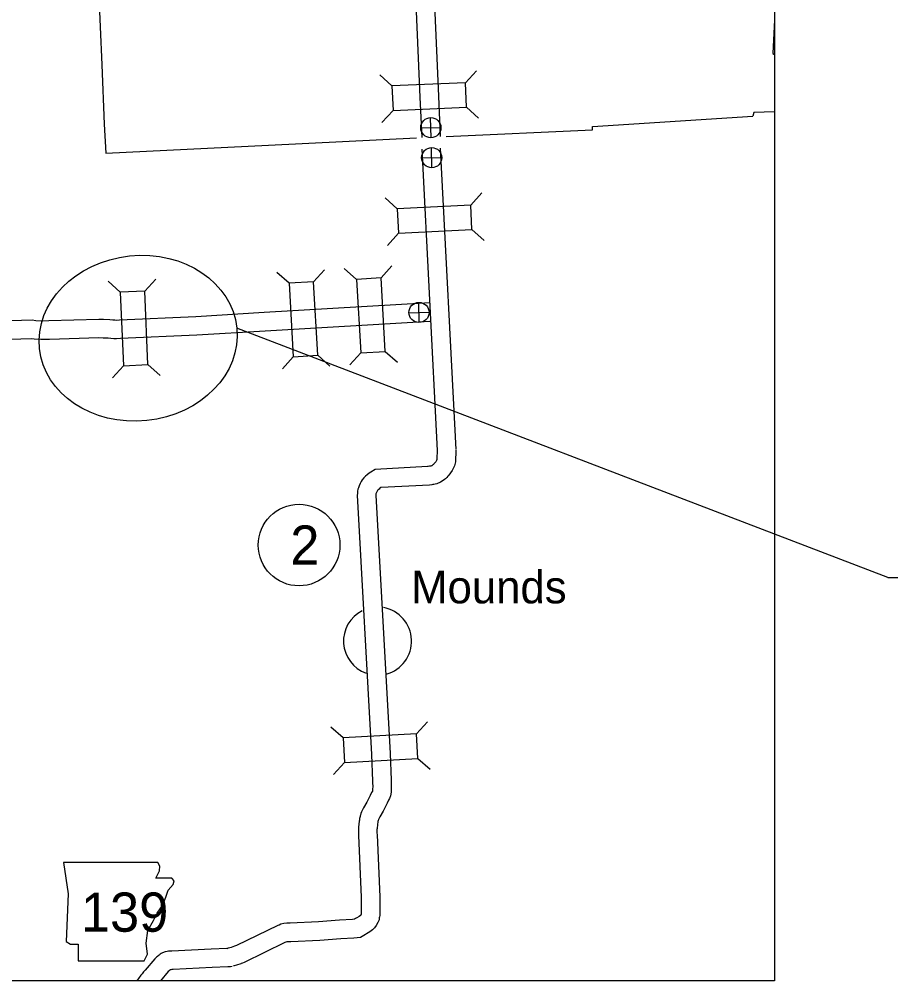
# Model space of a CAD drawing. Extents: x -0.3 to 2.65, y 0 to 1.9.
# Drawn here: x 0.2273 to 0.3593, y 0.5417 to 0.6874 of the extents above; entities that cross this region are included whole.
import ezdxf

# ---------------------------------------------------------------- set-up
doc = ezdxf.new("R2010")
doc.units = 0
for name, color, linetype in [('Default', 7, 'Continuous'), ('DSN_DRFT_DNC', 7, 'Continuous'), ('Level 21', 7, 'Continuous'), ('Level 22', 7, 'Continuous'), ('Level 23', 7, 'Continuous'), ('Level 24', 7, 'Continuous'), ('Level 38', 7, 'Continuous'), ('Level 39', 7, 'Continuous'), ('Level 59', 7, 'Continuous')]:
    doc.layers.add(name, color=color, linetype=linetype)

msp = doc.modelspace()

# ---------------------------------------------------------------- linework, layer by layer
at = {"layer": 'Default'}
for q in [(0.2602573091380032, 0.6405789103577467), (0.4503996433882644, 0.6027512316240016)]:
    msp.add_line((0.3588331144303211, 0.6027512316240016), q, dxfattribs=at)
msp.add_ellipse((0.2453091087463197, 0.6390280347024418), major_axis=(-0.014948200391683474, -0.001550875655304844), ratio=0.8342462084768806, dxfattribs=at)
at = {"layer": 'DSN_DRFT_DNC'}
msp.add_lwpolyline([(0.04166666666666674, 0.8750000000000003), (0.34166666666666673, 0.8750000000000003), (0.34166666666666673, 0.541666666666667), (0.04166666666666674, 0.541666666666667)], close=True, dxfattribs=at)
at = {"layer": 'Level 21'}
for points in [[(0.28712597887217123, 0.6956467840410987), (0.28799091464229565, 0.6755768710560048), (0.2882637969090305, 0.6694553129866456)], [(0.2900561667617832, 0.6929763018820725), (0.2908007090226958, 0.6757000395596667), (0.2910734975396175, 0.6695805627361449)], [(0.2882642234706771, 0.6676729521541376), (0.29059018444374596, 0.6220232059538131)], [(0.2910730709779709, 0.6678160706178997), (0.2933990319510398, 0.6221663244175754)], [(0.21786572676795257, 0.6414539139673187), (0.22926085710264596, 0.6417985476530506), (0.22980214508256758, 0.6417304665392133), (0.23059375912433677, 0.6416868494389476), (0.23179926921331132, 0.6417115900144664), (0.2393505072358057, 0.6419399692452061), (0.24008442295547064, 0.6419164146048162), (0.24100624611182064, 0.6418815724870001), (0.24147674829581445, 0.6418217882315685), (0.2417622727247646, 0.6417922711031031), (0.2419614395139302, 0.6417905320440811), (0.24246700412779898, 0.6418247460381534), (0.25404425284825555, 0.6423317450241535), (0.2643903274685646, 0.6429651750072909), (0.28953853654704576, 0.6444187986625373)], [(0.21797944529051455, 0.6386435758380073), (0.2291270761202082, 0.6389807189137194), (0.22954898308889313, 0.6389276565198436), (0.2305451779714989, 0.6388727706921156), (0.23187063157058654, 0.6388999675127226), (0.23934791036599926, 0.6391261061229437), (0.23998620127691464, 0.6391056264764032), (0.24077542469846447, 0.6390757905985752), (0.24115484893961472, 0.6390275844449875), (0.2416050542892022, 0.6389810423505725), (0.24204424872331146, 0.638977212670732), (0.2426235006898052, 0.6390164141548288), (0.25419172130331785, 0.6395230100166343), (0.2645574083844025, 0.6401576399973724), (0.28946698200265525, 0.6415974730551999)], [(0.29058864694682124, 0.6221231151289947), (0.290559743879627, 0.6206897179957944), (0.29055681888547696, 0.6206787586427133), (0.2904754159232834, 0.6205050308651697), (0.29038920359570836, 0.620322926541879), (0.2903571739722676, 0.6202702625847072), (0.29025673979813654, 0.620153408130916), (0.2900991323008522, 0.6199784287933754), (0.2900482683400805, 0.6199175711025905), (0.29003703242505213, 0.6199081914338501), (0.2899589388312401, 0.619842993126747), (0.28983800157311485, 0.6197529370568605), (0.2897699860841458, 0.6197042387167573), (0.2897179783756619, 0.6196844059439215), (0.28964814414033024, 0.6196683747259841), (0.28957408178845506, 0.6196505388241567), (0.28944164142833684, 0.6196349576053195), (0.28924751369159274, 0.6195903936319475), (0.2891357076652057, 0.6195711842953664), (0.2812175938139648, 0.6191630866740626), (0.28056831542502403, 0.6187568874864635), (0.28028590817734, 0.6185718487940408), (0.2799974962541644, 0.6183440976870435), (0.27974067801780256, 0.6181233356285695), (0.27947041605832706, 0.6178565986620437), (0.2792577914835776, 0.6175725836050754), (0.2790828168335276, 0.6173172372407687), (0.2789227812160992, 0.6170161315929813), (0.2787614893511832, 0.6166623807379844), (0.27866623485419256, 0.6163676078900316), (0.27860504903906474, 0.6161610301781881), (0.2785285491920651, 0.6158580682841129), (0.2785186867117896, 0.6154851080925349), (0.278504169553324, 0.6152674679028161), (0.2806499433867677, 0.5759751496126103), (0.2807959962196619, 0.571934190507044), (0.28081765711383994, 0.5715015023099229), (0.28083099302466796, 0.5712351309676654), (0.2808335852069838, 0.5710559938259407), (0.2808130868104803, 0.5707640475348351), (0.28081000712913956, 0.5705463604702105), (0.28078538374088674, 0.5704078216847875), (0.2806653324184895, 0.5701992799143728), (0.28046895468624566, 0.5697614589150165), (0.27996579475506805, 0.5687356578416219), (0.27942549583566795, 0.5678670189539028), (0.2792876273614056, 0.5675823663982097), (0.2792334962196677, 0.567458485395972), (0.27913804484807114, 0.5672547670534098), (0.27905685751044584, 0.5670093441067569), (0.27897919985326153, 0.5667819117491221), (0.2789516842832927, 0.5666418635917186), (0.27892695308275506, 0.5665594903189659), (0.27884590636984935, 0.5662671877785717), (0.27881712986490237, 0.5660168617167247), (0.27878967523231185, 0.5658430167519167), (0.2787623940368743, 0.5656240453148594), (0.27875565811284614, 0.5655330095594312), (0.27874535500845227, 0.5654323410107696), (0.2787301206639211, 0.5652890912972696), (0.27869461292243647, 0.5650611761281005), (0.278663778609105, 0.5647712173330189), (0.2786644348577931, 0.5645218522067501), (0.27865676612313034, 0.5642879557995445), (0.2786608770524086, 0.5639755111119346), (0.27867654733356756, 0.5636624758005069), (0.27908763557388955, 0.5543305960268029), (0.27909049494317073, 0.5537333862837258), (0.2791067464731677, 0.5519645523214), (0.2790964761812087, 0.5518524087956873), (0.2790929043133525, 0.5518213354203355), (0.27906870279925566, 0.5517075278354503), (0.27905845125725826, 0.5516426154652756), (0.2790373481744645, 0.5516048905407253), (0.2789656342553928, 0.5515390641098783), (0.2788017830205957, 0.5514078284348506), (0.2784425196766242, 0.5512042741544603), (0.2782471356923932, 0.5510771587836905), (0.27808660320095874, 0.5509778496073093), (0.27776322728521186, 0.5509525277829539), (0.2757790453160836, 0.5508244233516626), (0.27263609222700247, 0.550572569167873), (0.26832643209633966, 0.550393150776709), (0.2678209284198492, 0.5503780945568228), (0.26739261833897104, 0.5503318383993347), (0.2669039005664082, 0.5502453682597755), (0.26665681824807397, 0.5501140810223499), (0.26644114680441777, 0.550035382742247), (0.26021943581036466, 0.5470121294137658), (0.25990018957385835, 0.5468940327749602), (0.2594067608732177, 0.5467228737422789), (0.25918411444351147, 0.5466692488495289), (0.25893242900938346, 0.546611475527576), (0.2587252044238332, 0.5465303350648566)], [(0.2934005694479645, 0.6220664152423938), (0.29336481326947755, 0.6202930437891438), (0.2932097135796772, 0.619711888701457), (0.2930198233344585, 0.6193066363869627), (0.29286842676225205, 0.6189868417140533), (0.29264035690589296, 0.6186118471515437), (0.29236836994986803, 0.6182953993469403), (0.29222373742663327, 0.6181348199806), (0.29204441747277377, 0.6179202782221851), (0.2918394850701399, 0.6177491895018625), (0.2917014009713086, 0.6176339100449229), (0.2914966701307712, 0.6174814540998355), (0.29111174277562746, 0.6172058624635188), (0.2905376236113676, 0.616986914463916), (0.29029204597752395, 0.6169305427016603), (0.29006940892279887, 0.6168769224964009), (0.2899219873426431, 0.6168595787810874), (0.2898007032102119, 0.6168317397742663), (0.28944733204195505, 0.6167710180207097), (0.28209085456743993, 0.6163918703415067), (0.2820850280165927, 0.6163882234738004), (0.2819313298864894, 0.6162875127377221), (0.2817864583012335, 0.6161731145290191), (0.28164743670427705, 0.6160536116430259), (0.2815957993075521, 0.6160026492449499), (0.2815445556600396, 0.615934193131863), (0.28149216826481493, 0.6158577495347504), (0.28144638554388, 0.6157716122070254), (0.2813878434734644, 0.6156432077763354), (0.28135310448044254, 0.6155357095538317), (0.2813315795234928, 0.6154630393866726), (0.2813287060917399, 0.6153542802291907), (0.28132178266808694, 0.6152504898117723), (0.28345966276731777, 0.5761026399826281), (0.28360594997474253, 0.5720553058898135), (0.2836266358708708, 0.5716421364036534), (0.28364247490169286, 0.571325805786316), (0.28364750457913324, 0.5709776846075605), (0.28362418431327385, 0.5706455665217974), (0.2836189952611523, 0.5702786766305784), (0.28356021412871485, 0.5699478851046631), (0.2835251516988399, 0.5696889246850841), (0.2833845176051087, 0.5692771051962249), (0.2832283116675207, 0.5690141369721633), (0.2831735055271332, 0.5689189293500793), (0.28301534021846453, 0.5685663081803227), (0.28242863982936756, 0.5673702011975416), (0.28189205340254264, 0.5665075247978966), (0.28184282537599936, 0.5664058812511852), (0.2817959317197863, 0.5662985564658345), (0.2817557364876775, 0.5662127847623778), (0.2817228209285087, 0.5661132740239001), (0.2817022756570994, 0.5660531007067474), (0.28168492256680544, 0.5659647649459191), (0.2816292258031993, 0.5657792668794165), (0.2816148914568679, 0.565727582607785), (0.28160445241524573, 0.5656367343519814), (0.2815749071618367, 0.565449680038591), (0.28156202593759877, 0.5653462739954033), (0.28155756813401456, 0.5652859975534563), (0.281542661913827, 0.5651404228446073), (0.2815196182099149, 0.5649237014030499), (0.28148411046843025, 0.5646957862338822), (0.28147666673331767, 0.5646257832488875), (0.281477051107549, 0.5644794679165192), (0.2814698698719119, 0.5642603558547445), (0.28147244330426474, 0.5640643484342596), (0.2814859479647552, 0.5637946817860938), (0.2818998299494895, 0.5543992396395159), (0.281902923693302, 0.553753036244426), (0.28192042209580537, 0.5518489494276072), (0.28189428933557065, 0.551563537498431), (0.28187171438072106, 0.5513671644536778), (0.28183514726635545, 0.551195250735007), (0.2817908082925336, 0.550914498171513), (0.2816302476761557, 0.5504791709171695), (0.2813776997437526, 0.5500276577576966), (0.28112526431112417, 0.549703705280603), (0.28079774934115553, 0.5494030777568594), (0.28038420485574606, 0.549071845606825), (0.2799039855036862, 0.5487997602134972), (0.27975404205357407, 0.5487022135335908), (0.27898620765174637, 0.548227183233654), (0.2779636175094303, 0.5481471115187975), (0.2759819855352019, 0.5480191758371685), (0.27280697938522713, 0.5477647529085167), (0.26842679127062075, 0.5475824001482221), (0.2680140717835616, 0.5475701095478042), (0.26783757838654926, 0.5475510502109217), (0.267540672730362, 0.5474427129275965), (0.26137892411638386, 0.5444485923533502), (0.2611008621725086, 0.5443120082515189), (0.26091859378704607, 0.5442720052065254), (0.2608490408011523, 0.5442462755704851), (0.26019876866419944, 0.5440207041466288), (0.2598280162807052, 0.5439314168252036), (0.25976428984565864, 0.5439167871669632), (0.2597506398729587, 0.5439114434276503)], [(0.25890865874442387, 0.5465880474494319), (0.2588648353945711, 0.5465774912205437), (0.2587206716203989, 0.5465653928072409), (0.2563856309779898, 0.5464665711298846), (0.2503930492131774, 0.5461745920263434), (0.2501958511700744, 0.5461551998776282), (0.2498880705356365, 0.5461397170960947), (0.24970013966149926, 0.5460984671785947), (0.24940393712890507, 0.5460502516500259), (0.24899196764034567, 0.5458759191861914), (0.24880140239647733, 0.5457756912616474), (0.24862607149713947, 0.5456763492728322), (0.24846774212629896, 0.5455480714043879), (0.24834093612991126, 0.5454568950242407), (0.24823259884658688, 0.5453691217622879), (0.24806248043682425, 0.545242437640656), (0.24794617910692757, 0.5451133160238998), (0.24781579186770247, 0.5449907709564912), (0.24635164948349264, 0.5432741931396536), (0.24611728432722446, 0.5430248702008), (0.2458966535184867, 0.5427426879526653), (0.24572572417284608, 0.542518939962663), (0.24561964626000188, 0.5423684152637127), (0.24547074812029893, 0.5421635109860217), (0.24512000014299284, 0.5416666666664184)], [(0.259567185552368, 0.543853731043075), (0.25931430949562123, 0.5437928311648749), (0.25889781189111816, 0.5437578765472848), (0.25651352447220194, 0.5436569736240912), (0.25059924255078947, 0.5433688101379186), (0.25040426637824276, 0.5433496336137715), (0.2502803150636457, 0.5433433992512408), (0.25020137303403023, 0.543330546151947), (0.25004853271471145, 0.5432206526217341), (0.2499801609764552, 0.5431652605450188), (0.2498549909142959, 0.5430476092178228), (0.24867712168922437, 0.5416666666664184)]]:
    msp.add_lwpolyline(points, dxfattribs=at)
at = {"layer": 'Level 22'}
msp.add_lwpolyline([(0.34166666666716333, 0.6872970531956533), (0.34144081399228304, 0.6821589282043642), (0.34166666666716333, 0.6820177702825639)], dxfattribs=at)
msp.add_lwpolyline([(0.23401601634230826, 0.5595812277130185), (0.23472973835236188, 0.5548230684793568), (0.23441252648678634, 0.5476065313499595), (0.23504695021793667, 0.5472100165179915), (0.23623649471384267, 0.5472100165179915), (0.23623649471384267, 0.5446723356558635), (0.2462286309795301, 0.5446723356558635), (0.2467044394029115, 0.5457032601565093), (0.24654583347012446, 0.5473686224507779), (0.2467837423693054, 0.5492718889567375), (0.2476560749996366, 0.5507786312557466), (0.24821119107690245, 0.5518888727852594), (0.24900422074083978, 0.5530784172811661), (0.24948003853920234, 0.5543472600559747), (0.249876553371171, 0.5553781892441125), (0.2505902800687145, 0.5562505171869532), (0.25074888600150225, 0.5568056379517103), (0.25043167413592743, 0.5572021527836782), (0.2479732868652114, 0.5572021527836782), (0.24852840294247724, 0.5583123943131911), (0.24860770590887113, 0.5590261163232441), (0.24827883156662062, 0.5595742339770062)], close=True, dxfattribs=at)
at = {"layer": 'Level 23'}
for points in [[(0.23907959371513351, 0.7307290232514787), (0.23972831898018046, 0.7177264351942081), (0.23808092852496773, 0.717649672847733), (0.23929112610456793, 0.6920143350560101), (0.2397868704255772, 0.6804493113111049), (0.24017406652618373, 0.6714418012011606), (0.24039522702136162, 0.6670523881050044), (0.2650557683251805, 0.6682768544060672), (0.2874486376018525, 0.6694059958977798)], [(0.34166666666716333, 0.6733524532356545), (0.3385638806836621, 0.6732247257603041), (0.3383938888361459, 0.6726833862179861)], [(0.2919550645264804, 0.6696200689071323), (0.31411018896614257, 0.6706097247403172), (0.31410679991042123, 0.6710900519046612), (0.3383938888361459, 0.6726833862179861)]]:
    msp.add_lwpolyline(points, dxfattribs=at)
at = {"layer": 'Level 24'}
for start, end in [(116.98233333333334, 250.2859888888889), (284.74333333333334, 80.17801944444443)]:
    msp.add_arc((0.28156994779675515, 0.5931229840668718), 0.0051562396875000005, start, end, dxfattribs=at)
at = {"layer": 'Level 38'}
for p, q in [((0.2948794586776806, 0.6777327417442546), (0.2965525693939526, 0.6795565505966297)), ((0.2837523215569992, 0.6772532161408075), (0.28192851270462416, 0.6789263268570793)), ((0.28391216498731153, 0.673544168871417), (0.2822390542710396, 0.6717203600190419)), ((0.29503930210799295, 0.6740236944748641), (0.29686311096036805, 0.6723505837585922)), ((0.2845568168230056, 0.6586353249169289), (0.28271994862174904, 0.6602940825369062)), ((0.2956798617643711, 0.6592020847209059), (0.29733861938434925, 0.6610389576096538)), ((0.2847457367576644, 0.6549276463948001), (0.28308697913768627, 0.6530907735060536)), ((0.29586878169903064, 0.6554944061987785), (0.2977056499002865, 0.6538356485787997)), ((0.28209017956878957, 0.6481577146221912), (0.28373636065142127, 0.6500058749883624)), ((0.26816606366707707, 0.6473528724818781), (0.26631790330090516, 0.6489990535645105)), ((0.2718723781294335, 0.6475671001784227), (0.2735185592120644, 0.6494152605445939)), ((0.2783838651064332, 0.6479434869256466), (0.27653570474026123, 0.6495896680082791)), ((0.2426004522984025, 0.6459970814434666), (0.2407754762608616, 0.6476689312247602)), ((0.2463093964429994, 0.646159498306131), (0.24798124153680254, 0.6479844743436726)), ((0.27902654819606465, 0.636824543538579), (0.2773803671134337, 0.6349763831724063)), ((0.28273286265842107, 0.6370387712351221), (0.284581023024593, 0.6353925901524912)), ((0.26880874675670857, 0.6362339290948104), (0.26716256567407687, 0.6343857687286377)), ((0.27251506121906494, 0.6364481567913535), (0.27436322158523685, 0.6348019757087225)), ((0.24308770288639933, 0.6348702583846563), (0.2414158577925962, 0.6330452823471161)), ((0.2467966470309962, 0.6350326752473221), (0.2486216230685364, 0.6333608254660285)), ((0.27634541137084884, 0.5784624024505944), (0.2745025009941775, 0.580114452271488)), ((0.2874663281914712, 0.5790697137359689), (0.2891183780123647, 0.5809126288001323)), ((0.27654785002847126, 0.5747554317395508), (0.2748958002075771, 0.5729125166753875)), ((0.2876687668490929, 0.5753627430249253), (0.289511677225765, 0.5737106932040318))]:
    msp.add_line(p, q, dxfattribs=at)
for points in [[(0.2948794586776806, 0.6777327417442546), (0.2837523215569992, 0.6772532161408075), (0.28391216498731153, 0.673544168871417), (0.29503930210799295, 0.6740236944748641)], [(0.2847457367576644, 0.6549276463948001), (0.29586878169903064, 0.6554944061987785), (0.2956798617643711, 0.6592020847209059), (0.2845568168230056, 0.6586353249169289)], [(0.27251506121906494, 0.6364481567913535), (0.2718723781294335, 0.6475671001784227), (0.26816606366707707, 0.6473528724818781), (0.26880874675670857, 0.6362339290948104)], [(0.2783838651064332, 0.6479434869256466), (0.27902654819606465, 0.636824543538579), (0.28273286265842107, 0.6370387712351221), (0.28209017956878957, 0.6481577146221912)], [(0.2467966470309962, 0.6350326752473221), (0.2463093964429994, 0.646159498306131), (0.2426004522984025, 0.6459970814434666), (0.24308770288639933, 0.6348702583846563)], [(0.2874663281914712, 0.5790697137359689), (0.27634541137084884, 0.5784624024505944), (0.27654785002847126, 0.5747554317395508), (0.2876687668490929, 0.5753627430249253)]]:
    msp.add_lwpolyline(points, close=True, dxfattribs=at)
at = {"layer": 'Level 39'}
for p, q in [((0.28966894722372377, 0.6694095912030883), (0.28959855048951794, 0.6724609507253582)), ((0.28810806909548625, 0.6709000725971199), (0.29115942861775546, 0.6709704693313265)), ((0.28980443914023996, 0.6648620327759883), (0.2897340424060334, 0.6679133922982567)), ((0.28824356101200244, 0.6663525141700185), (0.2912949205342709, 0.6664229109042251)), ((0.2878771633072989, 0.64141146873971), (0.287806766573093, 0.6444628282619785)), ((0.2863162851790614, 0.6429019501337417), (0.28936764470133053, 0.6429723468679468))]:
    msp.add_line(p, q, dxfattribs=at)
for centre in [(0.28963374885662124, 0.6709352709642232), (0.28976924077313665, 0.6663877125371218), (0.2878419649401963, 0.6429371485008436)]:
    msp.add_circle(centre, 0.0015260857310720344, dxfattribs=at)
at = {"layer": 'Level 59'}
msp.add_circle((0.2696785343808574, 0.6076927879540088), 0.006187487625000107, dxfattribs=at)

# ---------------------------------------------------------------- texts
at = {"layer": 'Level 22'}
msp.add_text('139', height=0.005939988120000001, dxfattribs=at).set_placement((0.23662768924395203, 0.5490997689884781))
at = {"layer": 'Level 24'}
msp.add_text('Mounds', height=0.004949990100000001, dxfattribs=at).set_placement((0.28665386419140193, 0.5988551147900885))
at = {"layer": 'Level 59'}
msp.add_text('2', height=0.005939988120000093, dxfattribs=at).set_placement((0.26834979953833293, 0.6047227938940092))

doc.saveas('drawing.dxf')
